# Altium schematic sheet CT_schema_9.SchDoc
size 278 x 170 mm
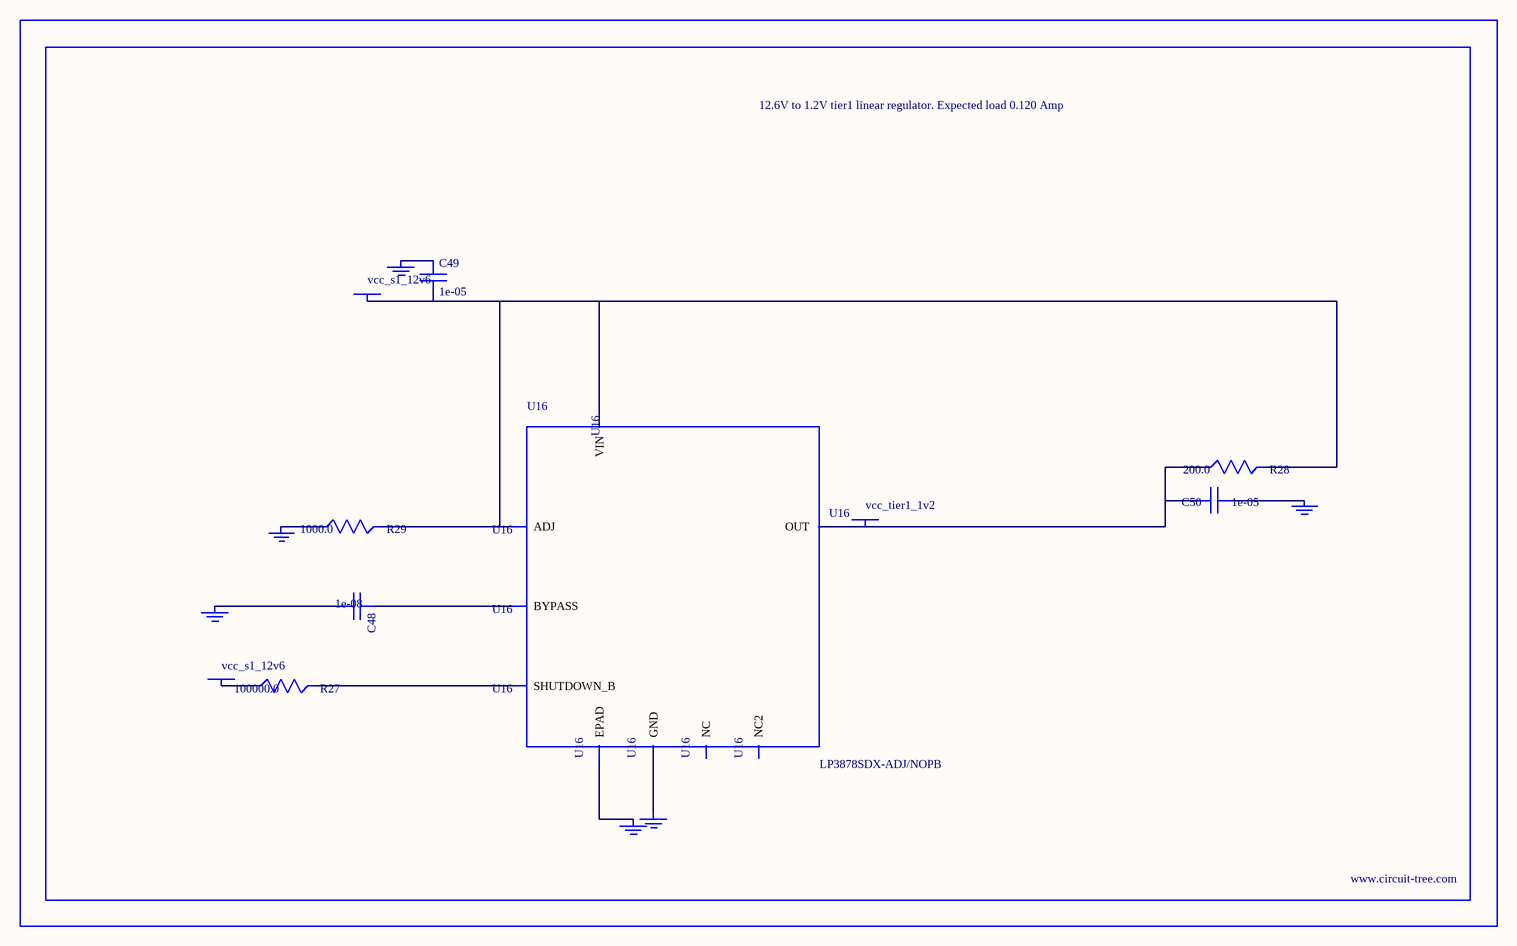
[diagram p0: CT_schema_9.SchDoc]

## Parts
BORDER8  (no value)
C48  1e-08  [C0402]
C49  1e-05  [C1210]
C50  1e-05  [C0805]
GND_INSTANCE_8_0  (no value)
GND_INSTANCE_8_1  (no value)
GND_INSTANCE_8_2  (no value)
GND_INSTANCE_8_3  (no value)
GND_INSTANCE_8_4  (no value)
GND_INSTANCE_8_5  (no value)
POWER_INSTANCE_8_0  vcc_s1_12v6
POWER_INSTANCE_8_1  vcc_s1_12v6
POWER_INSTANCE_8_2  vcc_tier1_1v2
R27  100000.0  [R0603]
R28  200.0  [R0603]
R29  1000.0  [R0603]
U16  LP3878SDX-ADJ/NOPB  [WSON-8]

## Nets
NetC48_1: C48.1 U16.1(BYPASS)
NetC48_2: C48.2 GND_INSTANCE_8_0.0(GND)
NetC49_1: C49.1 GND_INSTANCE_8_1.0(GND)
NetC49_2: C49.2 POWER_INSTANCE_8_0.0(PWR) R28.2 R29.2 U16.4(VIN) U16.6(ADJ)
NetC50_1: C50.1 GND_INSTANCE_8_2.0(GND)
NetC50_2: C50.2 POWER_INSTANCE_8_2.0(PWR) R28.1 U16.5(OUT)
NetGND_INSTANCE_8_3_0: GND_INSTANCE_8_3.0(GND) R29.1
NetGND_INSTANCE_8_4_0: GND_INSTANCE_8_4.0(GND) U16.PAD(EPAD)
NetGND_INSTANCE_8_5_0: GND_INSTANCE_8_5.0(GND) U16.3(GND)
NetPOWER_INSTANCE_8_1_0: POWER_INSTANCE_8_1.0(PWR) R27.1
NetR27_2: R27.2 U16.8(SHUTDOWN_B)

Not connected (* = marked no-connect by the designer): U16 2(NC) 7(NC2)

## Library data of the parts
BORDER8 = BORDER_PAGE8
C48 = C0402C103K3RAC
C49 = C1210C106K5PACTU
C50 = GRM219R60J106ME19D
GND_INSTANCE_8_0-GND_INSTANCE_8_5 = GND
POWER_INSTANCE_8_0-POWER_INSTANCE_8_2 = PWR
R27 = RC0603JR-07100KL
R28 = RC0603JR-07200RL
R29 = RC0603JR-071KL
